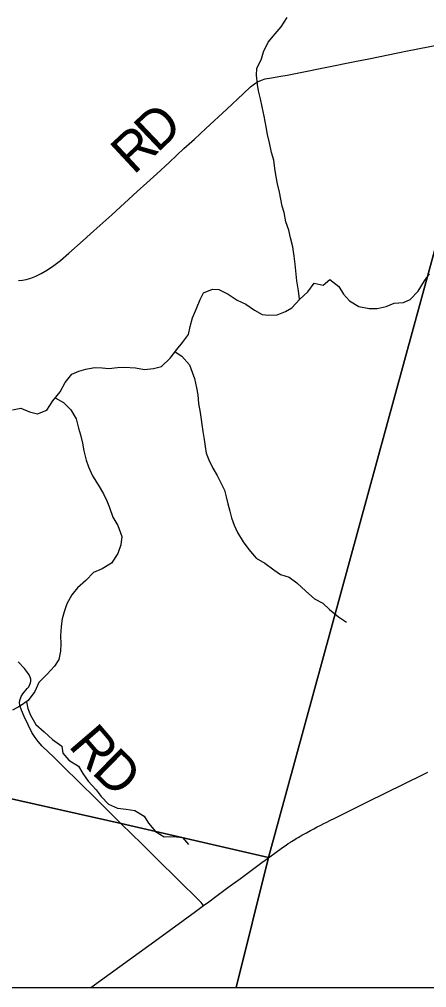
# Model space of a CAD drawing. Extents: x 0 to 34, y 0 to 22.
# Drawn here: x 22.346 to 22.942, y 14.306 to 15.724 of the extents above; entities that cross this region are included whole.
import ezdxf

# ---------------------------------------------------------------- set-up
doc = ezdxf.new("R2010")
doc.units = 0
for name, color, linetype in [('GM_X_Corporation', 7, 'Continuous'), ('GM_X_County_Road', 7, 'Continuous'), ('GM_X_Minor_River', 7, 'Continuous'), ('GM_X_Township_Road', 7, 'Continuous'), ('GM_X_Township_Road_Text', 7, 'Continuous')]:
    doc.layers.add(name, color=color, linetype=linetype)

msp = doc.modelspace()

# ---------------------------------------------------------------- linework, layer by layer
at = {"layer": 'GM_X_Corporation'}
for points in [[(17.597, 14.3059), (23.9625, 14.3059), (23.9625, 21.1059), (18.23, 21.1059), (18.203, 20.7746), (18.1731, 20.4696), (18.0879, 19.5959), (18.0387, 19.0962), (17.9672, 18.2605), (17.8718, 17.2256), (17.7834, 16.317), (17.7373, 15.7617), (17.7239, 15.6245), (17.6136, 14.4601)], [(22.6629, 14.3059), (23.9625, 14.3059), (23.9625, 18.7666), (23.8567, 18.7798), (23.8507, 18.7519), (23.7107, 18.1304), (23.6615, 17.9524), (23.566, 17.6066), (23.5619, 17.5912), (23.4462, 17.1725), (23.362, 16.8676), (23.1639, 16.2517), (23.0409, 15.7041), (22.7103, 14.4966)], [(17.597, 14.3059), (22.6629, 14.3059), (22.7103, 14.4966), (22.4946, 14.5463), (21.6235, 14.742), (20.9871, 14.8793), (20.156, 15.0595), (18.8797, 15.3563), (18.0639, 15.5437), (17.7239, 15.6245), (17.6136, 14.4601)]]:
    msp.add_lwpolyline(points, close=True, dxfattribs=at)
msp.add_lwpolyline([(17.8718, 17.2256), (17.7834, 16.317), (17.7373, 15.7617), (17.7239, 15.6245), (18.0639, 15.5437), (18.8797, 15.3563), (20.156, 15.0595), (20.9871, 14.8793), (21.6235, 14.742), (22.4946, 14.5463), (22.7103, 14.4966), (23.0409, 15.7041), (23.1639, 16.2517), (23.362, 16.8676)], dxfattribs=at)
at = {"layer": 'GM_X_County_Road'}
for points in [[(22.7105, 14.4961), (22.7235, 14.5057), (22.7325, 14.512), (22.7362, 14.5146), (22.7392, 14.5168), (22.742, 14.5186), (22.7432, 14.5194), (22.7441, 14.52), (22.7466, 14.5215), (22.749, 14.523), (22.751, 14.5242), (22.7536, 14.5256), (22.7563, 14.5272), (22.7594, 14.5289), (22.7661, 14.5327), (22.7718, 14.5358), (22.777, 14.5386), (22.7818, 14.5412), (22.7869, 14.5438), (22.7915, 14.5462), (22.7958, 14.5484), (22.8002, 14.5506), (22.8075, 14.5542), (22.8495, 14.5749), (22.8882, 14.594), (22.9033, 14.6014), (22.9439, 14.6215)], [(22.6151, 14.426), (22.6229, 14.4317), (22.6334, 14.4394), (22.651, 14.4523), (22.6695, 14.4658), (22.6849, 14.4773), (22.6929, 14.4833), (22.7007, 14.489), (22.7105, 14.4961)], [(22.4502, 14.3059), (22.5211, 14.3573), (22.5493, 14.3776), (22.6033, 14.4174), (22.6151, 14.426)]]:
    msp.add_lwpolyline(points, dxfattribs=at)
at = {"layer": 'GM_X_Minor_River'}
for points in [[(22.756, 15.3139), (22.7545, 15.3263), (22.7517, 15.3411), (22.7507, 15.3506), (22.7494, 15.3655), (22.7481, 15.3772), (22.746, 15.3906), (22.7424, 15.4039), (22.7403, 15.4149), (22.7359, 15.4275), (22.7331, 15.4409), (22.7306, 15.4504), (22.7284, 15.4607), (22.7267, 15.4706), (22.7234, 15.4831), (22.7217, 15.493), (22.7196, 15.5056), (22.7183, 15.5177), (22.715, 15.5288), (22.7118, 15.5429), (22.7089, 15.5551), (22.7068, 15.5665), (22.704, 15.5821), (22.7012, 15.5958), (22.6987, 15.6072), (22.6958, 15.619), (22.6945, 15.6285), (22.6928, 15.6419), (22.6933, 15.6517), (22.7003, 15.666), (22.7031, 15.6763), (22.7098, 15.6906), (22.7202, 15.7026), (22.7287, 15.7131), (22.7376, 15.7267)], [(22.3357, 15.1521), (22.3478, 15.1542), (22.3603, 15.1491), (22.372, 15.1462), (22.3857, 15.1517), (22.3946, 15.1653), (22.4054, 15.1784), (22.4125, 15.192), (22.4225, 15.2044), (22.4328, 15.2084), (22.4427, 15.2117), (22.4556, 15.2138), (22.4666, 15.2133), (22.4768, 15.2124), (22.4894, 15.2141), (22.4996, 15.2144), (22.5155, 15.2134), (22.5288, 15.2113), (22.5421, 15.2123), (22.5539, 15.2155), (22.5665, 15.2275), (22.5762, 15.2403), (22.5843, 15.2504), (22.5932, 15.2624), (22.5957, 15.2742), (22.5993, 15.2866), (22.6051, 15.3002), (22.6103, 15.3135), (22.6153, 15.3233), (22.6283, 15.3288), (22.6378, 15.3283), (22.6513, 15.3212), (22.6645, 15.3127), (22.6773, 15.3065), (22.6897, 15.2979), (22.7009, 15.2917), (22.7108, 15.2908), (22.7229, 15.291), (22.7351, 15.2958), (22.7447, 15.3014), (22.7563, 15.3141), (22.7682, 15.325), (22.7771, 15.3374), (22.7903, 15.3345), (22.8003, 15.3428), (22.8134, 15.3327), (22.8204, 15.3212), (22.829, 15.3116), (22.8425, 15.3031), (22.8577, 15.3002), (22.8694, 15.3004), (22.8827, 15.3033), (22.8946, 15.3081), (22.9082, 15.3094), (22.9178, 15.3134), (22.9293, 15.3258), (22.9386, 15.3409), (22.946, 15.3514)], [(22.5735, 15.2367), (22.5837, 15.2307), (22.5948, 15.218), (22.5985, 15.2073), (22.6018, 15.1978), (22.605, 15.1841), (22.6071, 15.1738), (22.6081, 15.1612), (22.6101, 15.1483), (22.6143, 15.1202), (22.616, 15.1087), (22.6178, 15.0981), (22.6191, 15.0886), (22.6228, 15.079), (22.6291, 15.0668), (22.635, 15.0557), (22.6401, 15.0462), (22.646, 15.0343), (22.6485, 15.0248), (22.6507, 15.0145), (22.6539, 15.0035), (22.6564, 14.9939), (22.6601, 14.9829), (22.6648, 14.9722), (22.6734, 14.9588), (22.6815, 14.9473), (22.6924, 14.935), (22.7051, 14.9276), (22.7183, 14.9179), (22.728, 14.9109), (22.7405, 14.907), (22.7521, 14.8989), (22.7652, 14.8865), (22.7779, 14.8753), (22.79, 14.8691), (22.7997, 14.8595), (22.8128, 14.8491), (22.8245, 14.8413)], [(22.3981, 15.1695), (22.4101, 15.1628), (22.421, 15.152), (22.4288, 15.139), (22.4324, 15.1253), (22.4352, 15.1154), (22.4381, 15.1032), (22.4402, 15.0922), (22.4434, 15.0785), (22.4467, 15.0685), (22.4529, 15.0552), (22.4611, 15.0421), (22.4689, 15.0291), (22.4737, 15.0188), (22.4777, 15.0089), (22.4824, 14.9948), (22.4898, 14.9825), (22.4956, 14.9665), (22.494, 14.9544), (22.4896, 14.9415), (22.4803, 14.9276), (22.4669, 14.9191), (22.4539, 14.9139), (22.4428, 14.9023), (22.4309, 14.8915), (22.4224, 14.8813), (22.415, 14.8681), (22.411, 14.856), (22.4082, 14.8458), (22.4069, 14.8348), (22.4056, 14.8212), (22.4062, 14.8094), (22.406, 14.7988), (22.4035, 14.7863), (22.397, 14.7765), (22.3862, 14.7649), (22.3742, 14.7529), (22.3684, 14.7397), (22.3587, 14.7262), (22.3472, 14.7187), (22.3354, 14.7121)], [(22.3562, 14.7246), (22.3581, 14.7144), (22.3618, 14.7049), (22.3699, 14.6911), (22.3819, 14.6807), (22.3939, 14.6691), (22.4078, 14.6594), (22.4091, 14.6492), (22.4181, 14.6392), (22.432, 14.6303), (22.4383, 14.6195), (22.4461, 14.6084), (22.458, 14.5954), (22.4655, 14.5858), (22.4759, 14.5746), (22.4895, 14.5687), (22.502, 14.567), (22.5148, 14.5653), (22.5284, 14.5572), (22.5347, 14.5465), (22.5447, 14.5346), (22.5575, 14.5268), (22.5715, 14.527), (22.5844, 14.5257), (22.593, 14.5153)]]:
    msp.add_lwpolyline(points, dxfattribs=at)
at = {"layer": 'GM_X_Township_Road'}
for points in [[(22.3444, 15.3413), (22.35, 15.3417), (22.3554, 15.3428), (22.3625, 15.3449), (22.3699, 15.3479), (22.3777, 15.3518), (22.3867, 15.3571), (22.3959, 15.3634), (22.4058, 15.3709), (22.4181, 15.3813), (22.4388, 15.4), (22.4546, 15.4141), (22.4808, 15.4378), (22.518, 15.4717), (22.5324, 15.4846), (22.5467, 15.4975), (22.5648, 15.5144), (22.5761, 15.525), (22.5866, 15.5347), (22.6018, 15.5485), (22.6188, 15.5639), (22.6492, 15.5923), (22.6732, 15.6149), (22.6842, 15.625), (22.6897, 15.6292), (22.6944, 15.6322), (22.7001, 15.6349), (22.7056, 15.6365), (22.7148, 15.6382), (22.7282, 15.6405), (22.7377, 15.6422), (22.755, 15.6456), (22.7958, 15.6538), (22.8367, 15.6619), (22.8599, 15.6665), (22.9116, 15.677), (22.9292, 15.6807), (22.964, 15.6876)], [(22.4948, 14.5458), (22.4575, 14.5827), (22.4098, 14.6299), (22.396, 14.6433), (22.3791, 14.6596), (22.373, 14.6664), (22.3686, 14.6721), (22.364, 14.6795), (22.3583, 14.6906), (22.3524, 14.703), (22.3486, 14.7123), (22.3469, 14.7176), (22.3463, 14.7199), (22.3459, 14.7231), (22.3462, 14.7263), (22.347, 14.7294), (22.3483, 14.7323), (22.3508, 14.7359), (22.357, 14.7437), (22.3592, 14.7466), (22.3611, 14.7497), (22.3621, 14.7524), (22.3625, 14.7548), (22.3623, 14.7577), (22.3616, 14.7606), (22.36, 14.7639), (22.3577, 14.7675), (22.353, 14.7732), (22.3437, 14.7832)], [(22.6151, 14.426), (22.6133, 14.4284), (22.6117, 14.4304), (22.6103, 14.4321), (22.6088, 14.4336), (22.5782, 14.4635), (22.5473, 14.4941), (22.5248, 14.5164), (22.4948, 14.5458)]]:
    msp.add_lwpolyline(points, dxfattribs=at)

# ---------------------------------------------------------------- texts
at = {"layer": 'GM_X_Township_Road_Text'}
for s, rotation, p in [('D', 43.6043, (22.5476, 15.5274)), ('R', 42.9269, (22.5129, 15.4951)), ('R', 310.6656, (22.4161, 14.6597)), ('D', 315.6542, (22.4501, 14.6204))]:
    msp.add_text(s, height=0.0568, rotation=rotation, dxfattribs=at).set_placement(p)

doc.saveas('drawing.dxf')
